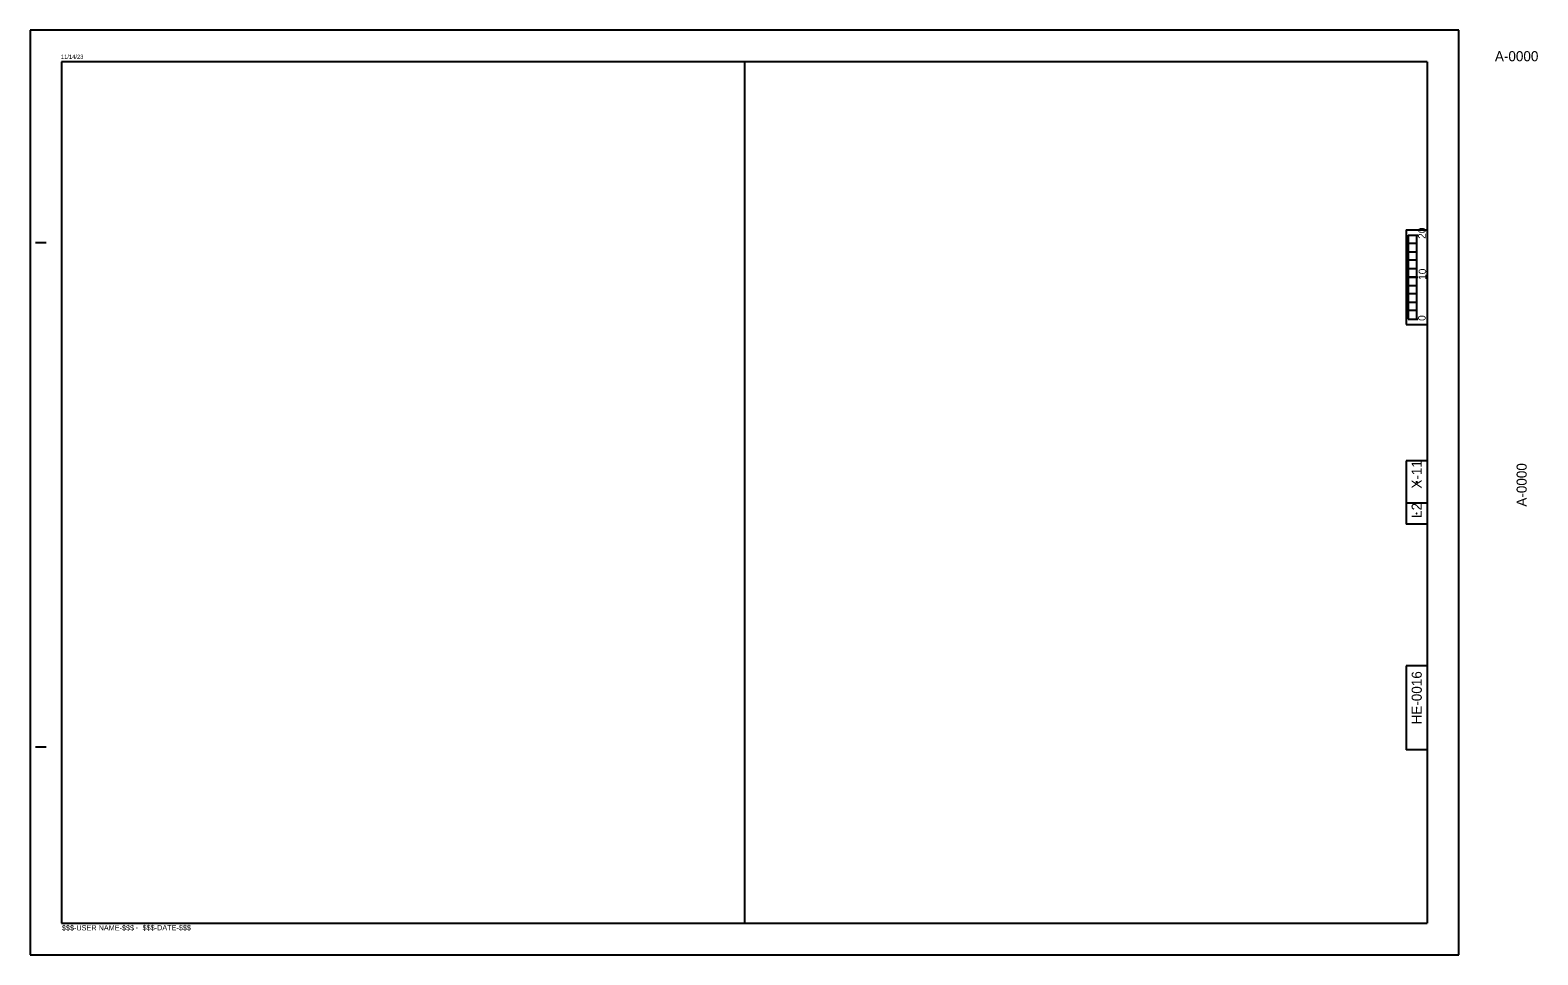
# Model space of a CAD drawing. Extents: x -2.69 to 2.99, y 0 to 1.83.
# Drawn here: x 0 to 2.99, y 0 to 1.833 of the extents above; entities that cross this region are included whole.
import ezdxf

# ---------------------------------------------------------------- set-up
doc = ezdxf.new("R2010")
doc.units = 0
for name, color, linetype in [('_CIVIL_CONSTRUCTION', 7, 'Continuous'), ('P_NCDOT_XS_Label_Slope_Superelevation', 7, 'Continuous'), ('P_NCDOT_XS_Leader_Line', 7, 'Continuous'), ('P_NCDOT_XS_Sheet_Alignment_Station_Label', 7, 'Continuous'), ('P_NCDOT_XS_Slope_Label', 7, 'Continuous')]:
    doc.layers.add(name, color=color, linetype=linetype)

msp = doc.modelspace()

# ---------------------------------------------------------------- linework, layer by layer
at = {"layer": 'P_NCDOT_XS_Label_Slope_Superelevation'}
for p, q in [((0.0625, 1.7708), (0.0625, 0.0625)), ((2.7708, 1.7708), (0.0625, 1.7708)), ((0.1027, 1.7844), (0.1027, 1.7844)), ((2.7708, 1.7708), (2.7708, 0.0625)), ((2.7292, 1.4375), (2.7292, 1.25)), ((2.7292, 1.4375), (2.7708, 1.4375)), ((0.0108, 1.4125), (0.0317, 1.4126)), ((2.7292, 1.25), (2.7708, 1.25)), ((2.7292, 0.9792), (2.7292, 0.8542)), ((2.7708, 0.9792), (2.7292, 0.9792)), ((2.7708, 0.8958), (2.7292, 0.8958)), ((2.7708, 0.8542), (2.7292, 0.8542)), ((2.7292, 0.5729), (2.7292, 0.4062)), ((2.7708, 0.5729), (2.7292, 0.5729)), ((0.0109, 0.4125), (0.0317, 0.4125)), ((2.7708, 0.4062), (2.7292, 0.4062)), ((0.0625, 0.0625), (2.7708, 0.0625))]:
    msp.add_line(p, q, dxfattribs=at)
at = {"layer": 'P_NCDOT_XS_Leader_Line'}
for p, q in [((2.8333, 1.8333), (0, 1.8333)), ((0, 1.8333), (0, 0)), ((2.8333, 0), (2.8333, 1.8333)), ((1.4167, 1.7708), (1.4166, 0.0625)), ((0, 0), (2.8333, 0))]:
    msp.add_line(p, q, dxfattribs=at)
for centre in [(2.7499, 1.3437), (2.7499, 0.9375), (2.7499, 0.875), (2.75, 0.4897)]:
    msp.add_circle(centre, 0.0001, dxfattribs=at)
at = {"layer": 'P_NCDOT_XS_Sheet_Alignment_Station_Label'}
for p, q in [((2.7332, 1.4272), (2.7521, 1.4272)), ((2.7332, 1.4272), (2.7332, 1.2605)), ((2.7416, 1.4272), (2.7503, 1.4272)), ((2.7499, 1.4272), (2.7499, 1.2605)), ((2.7332, 1.3438), (2.7521, 1.3438)), ((2.7332, 1.2605), (2.7521, 1.2605)), ((2.7416, 1.2605), (2.7503, 1.2605))]:
    msp.add_line(p, q, dxfattribs=at)
for points in [[(2.7332, 1.4272), (2.7499, 1.4272), (2.7499, 1.4105), (2.7332, 1.4105)], [(2.7332, 1.3938), (2.7499, 1.3938), (2.7499, 1.3772), (2.7332, 1.3772)], [(2.7332, 1.3605), (2.7499, 1.3605), (2.7499, 1.3438), (2.7332, 1.3438)], [(2.7332, 1.3272), (2.7499, 1.3272), (2.7499, 1.3105), (2.7332, 1.3105)], [(2.7332, 1.2938), (2.7499, 1.2938), (2.7499, 1.2772), (2.7332, 1.2772)]]:
    msp.add_lwpolyline(points, close=True, dxfattribs=at)

# ---------------------------------------------------------------- texts
at = {"layer": '_CIVIL_CONSTRUCTION'}
for s, p in [('X-11', (2.7599, 0.9243)), ('L2', (2.7599, 0.8662))]:
    msp.add_text(s, height=0.02, rotation=90, dxfattribs=at).set_placement(p)
at = {"layer": 'P_NCDOT_XS_Label_Slope_Superelevation'}
msp.add_text('11/14/23', height=0.00833, rotation=0, dxfattribs=at).set_placement((0.0609, 1.7764))
for s, height, p in [('$$$-DATE-$$$', 0.010417, (0.223, 0.0486)), ('$$$-USER NAME-$$$', 0.010417, (0.063, 0.0484)), ('-', 0.0104, (0.2093, 0.0494))]:
    msp.add_text(s, height=height, dxfattribs=at).set_placement(p)
at = {"layer": 'P_NCDOT_XS_Sheet_Alignment_Station_Label'}
for s, p in [('20', (2.7678, 1.4196)), ('10', (2.7688, 1.3382)), ('0', (2.7677, 1.2569))]:
    msp.add_text(s, height=0.015, rotation=90, dxfattribs=at).set_placement(p)
at = {"layer": 'P_NCDOT_XS_Slope_Label'}
msp.add_text('A-0000', height=0.02, dxfattribs=at).set_placement((2.9051, 1.7717))
for s, p in [('A-0000', (2.9681, 0.8886)), ('HE-0016', (2.76, 0.4568))]:
    msp.add_text(s, height=0.02, rotation=90, dxfattribs=at).set_placement(p)

doc.saveas('drawing.dxf')
